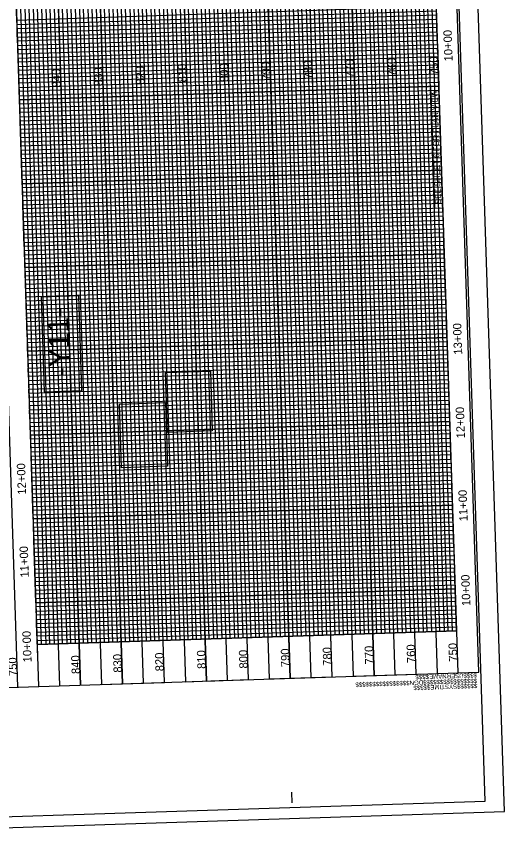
# Model space of a CAD drawing. Extents: x 1627314 to 1628469, y 762309 to 764253.
# Drawn here: x 1627888 to 1628469, y 762309 to 763293 of the extents above; entities that cross this region are included whole.
import ezdxf

# ---------------------------------------------------------------- set-up
doc = ezdxf.new("R2010")
doc.units = 0
for name, color, linetype in [('Exist Vertical Profile Horizontal Axis Label Major', 7, 'Continuous'), ('Exist Vertical Profile Vertical Axis Label', 7, 'Continuous'), ('Prop DSN Text', 7, 'Continuous'), ('Prop Grid Mask', 7, 'Continuous'), ('Sheet Data Field CELL', 7, 'Continuous'), ('Sheet DOT Grid CELL', 7, 'Continuous'), ('Sheet Layout Profile Border Port 2', 7, 'Continuous'), ('Sheet Plot Border Inside CELL', 7, 'Continuous'), ('Sheet Plot Border Outside CELL', 7, 'Continuous'), ('Sheet Profile CELL', 7, 'Continuous'), ('Sheet Profile Grid Major CELL', 7, 'Continuous'), ('Sheet Profile Grid Middle CELL', 7, 'Continuous'), ('Sheet Profile Grid Minor CELL', 7, 'Continuous')]:
    doc.layers.add(name, color=color, linetype=linetype)

msp = doc.modelspace()

# ---------------------------------------------------------------- linework, layer by layer
at = {"layer": 'Prop Grid Mask'}
for points in [[(1627891.16, 763193.83), (1627889.52, 763243.8), (1628389.25, 763260.15), (1628390.89, 763210.18)], [(1628380.89, 763209.85), (1628385.63, 763064.93), (1628395.63, 763065.25), (1628390.89, 763210.18)], [(1627965.43, 762847.15), (1627961.73, 762960.18), (1627917.01, 762958.71), (1627920.71, 762845.69)], [(1628067.5, 762797.23), (1628065.17, 762868.61), (1628118.63, 762870.36), (1628120.96, 762798.98)], [(1628012.62, 762755.07), (1628010.14, 762831.14), (1628065.23, 762832.94), (1628067.71, 762756.87)]]:
    msp.add_lwpolyline(points, close=True, dxfattribs=at)
at = {"layer": 'Sheet DOT Grid CELL'}
for p, q in [((1628163.91, 762502.38), (1628114.87, 764001.46)), ((1628213.88, 762504.01), (1628164.85, 764003.1)), ((1628263.85, 762505.65), (1628214.82, 764004.73)), ((1628313.83, 762507.28), (1628264.79, 764006.37)), ((1628363.8, 762508.92), (1628314.77, 764008)), ((1627914.04, 762494.2), (1627865.01, 763993.29)), ((1627964.01, 762495.84), (1627914.98, 763994.92)), ((1628013.99, 762497.47), (1627964.95, 763996.56)), ((1628063.96, 762499.11), (1628014.93, 763998.19)), ((1628113.93, 762500.74), (1628064.9, 763999.83)), ((1627889.52, 763243.8), (1628389.25, 763260.15)), ((1627891.16, 763193.83), (1628390.89, 763210.18)), ((1627892.79, 763143.86), (1628392.52, 763160.2)), ((1627894.43, 763093.88), (1628394.16, 763110.23)), ((1627896.06, 763043.91), (1628395.79, 763060.26)), ((1627897.69, 762993.94), (1628397.43, 763010.28)), ((1627899.33, 762943.96), (1628399.06, 762960.31)), ((1627900.96, 762893.99), (1628400.7, 762910.34)), ((1627902.6, 762844.02), (1628402.33, 762860.36)), ((1627904.23, 762794.04), (1628403.97, 762810.39)), ((1627905.87, 762744.07), (1628405.6, 762760.42)), ((1627907.5, 762694.1), (1628407.24, 762710.44)), ((1627909.14, 762644.12), (1628408.87, 762660.47)), ((1627910.77, 762594.15), (1628410.5, 762610.5)), ((1627912.41, 762544.18), (1628412.14, 762560.52))]:
    msp.add_line(p, q, dxfattribs=at)
at = {"layer": 'Sheet Layout Profile Border Port 2'}
msp.add_lwpolyline([(1627912.41, 762544.18), (1627866.64, 763943.43), (1628366.37, 763959.78), (1628412.14, 762560.52)], close=True, dxfattribs=at)
at = {"layer": 'Sheet Plot Border Inside CELL'}
msp.add_lwpolyline([(1628446.34, 762357.53), (1628391.86, 764023.14), (1627337.33, 763988.65), (1627391.81, 762323.04)], close=True, dxfattribs=at)
at = {"layer": 'Sheet Plot Border Outside CELL'}
msp.add_lwpolyline([(1628469.21, 762345.27), (1628413.63, 764044.37), (1627314.22, 764008.4), (1627369.79, 762309.31)], close=True, dxfattribs=at)
at = {"layer": 'Sheet Profile CELL'}
for p, q in [((1628364.74, 764009.75), (1628413.77, 762510.55)), ((1628438.76, 762511.37), (1628389.72, 764010.57)), ((1627889.05, 762493.39), (1627840.02, 763992.59)), ((1627914.04, 762494.2), (1627865, 763993.4)), ((1628438.76, 762511.37), (1628438.76, 762511.37)), ((1628438.76, 762511.37), (1628438.76, 762511.37)), ((1628438.76, 762511.37), (1628438.76, 762511.37)), ((1628438.76, 762511.37), (1628438.76, 762511.37)), ((1628438.76, 762511.37), (1628438.76, 762511.37)), ((1628438.76, 762511.37), (1628438.76, 762511.37)), ((1628438.76, 762511.37), (1628438.76, 762511.37)), ((1628216.24, 762355.51), (1628215.83, 762368))]:
    msp.add_line(p, q, dxfattribs=at)
msp.add_lwpolyline([(1627340.28, 763976.24), (1627389.32, 762477.04), (1628438.76, 762511.37), (1628389.72, 764010.57)], close=True, dxfattribs=at)
msp.add_lwpolyline([(1628437.53, 762548.85), (1628437.53, 762548.85)], dxfattribs=at)
at = {"layer": 'Sheet Profile Grid Major CELL'}
for p, q in [((1627891.16, 763193.83), (1627889.52, 763243.8)), ((1627894.43, 763093.88), (1627892.79, 763143.86)), ((1627897.69, 762993.94), (1627896.06, 763043.91)), ((1628413.77, 762510.55), (1628413.77, 762510.55))]:
    msp.add_line(p, q, dxfattribs=at)
for points in [[(1628064.9, 763999.94), (1628113.93, 762500.74), (1628163.91, 762502.38), (1628114.87, 764001.58)], [(1628164.84, 764003.21), (1628213.88, 762504.01), (1628263.85, 762505.65), (1628214.82, 764004.85)], [(1628264.79, 764006.48), (1628313.83, 762507.28), (1628313.83, 762507.28), (1628363.8, 762508.92), (1628314.76, 764008.11)], [(1628364.74, 764009.75), (1628413.77, 762510.55)], [(1627914.98, 763995.04), (1627964.01, 762495.84)], [(1627964.95, 763996.67), (1628013.99, 762497.47), (1628063.96, 762499.11), (1628014.92, 763998.31)], [(1627912.41, 762544.18), (1628412.14, 762560.52), (1628410.5, 762610.5), (1627910.77, 762594.15), (1627909.14, 762644.12), (1628408.87, 762660.47), (1628407.24, 762710.44), (1627907.5, 762694.1), (1627905.87, 762744.07), (1628405.6, 762760.42), (1628403.97, 762810.39), (1627904.23, 762794.04), (1627902.6, 762844.02), (1628402.33, 762860.36), (1628400.7, 762910.34), (1627900.96, 762893.99), (1627899.33, 762943.96), (1628399.06, 762960.31), (1628397.43, 763010.28), (1627897.69, 762993.94), (1627896.06, 763043.91), (1628395.79, 763060.26), (1628394.16, 763110.23), (1627894.43, 763093.88), (1627892.79, 763143.86), (1628392.52, 763160.2), (1628390.89, 763210.18), (1627891.16, 763193.83), (1627889.52, 763243.8), (1628389.25, 763260.15), (1628387.62, 763310.12)]]:
    msp.add_lwpolyline(points, dxfattribs=at)
at = {"layer": 'Sheet Profile Grid Middle CELL'}
for points in [[(1628139.86, 764002.39), (1628188.89, 762503.2), (1628238.87, 762504.83), (1628189.83, 764004.03)], [(1628239.8, 764005.66), (1628288.84, 762506.46), (1628338.81, 762508.1), (1628289.78, 764007.3)], [(1628339.75, 764008.93), (1628388.79, 762509.73)], [(1627939.03, 762495.02), (1627889.99, 763994.22)], [(1627939.96, 763995.85), (1627989, 762496.66), (1628038.97, 762498.29), (1627989.94, 763997.49)], [(1628039.91, 763999.12), (1628088.95, 762499.93), (1628138.92, 762501.56), (1628089.88, 764000.76)], [(1627913.22, 762519.19), (1627911.59, 762569.16), (1628411.32, 762585.51), (1628409.69, 762635.48), (1627909.95, 762619.14), (1627908.32, 762669.11), (1628408.05, 762685.46), (1628406.42, 762735.43), (1627906.69, 762719.08), (1627905.05, 762769.06), (1628404.78, 762785.4), (1628403.15, 762835.38), (1627903.42, 762819.03), (1627901.78, 762869), (1628401.51, 762885.35), (1628399.88, 762935.32), (1627900.15, 762918.98), (1627898.51, 762968.95), (1628398.24, 762985.3), (1628396.61, 763035.27), (1627896.88, 763018.92), (1627895.24, 763068.9), (1628394.98, 763085.24), (1628393.34, 763135.22), (1628393.34, 763135.22), (1627893.61, 763118.87), (1627891.97, 763168.84), (1628391.71, 763185.19), (1628390.07, 763235.16), (1627890.34, 763218.82), (1627888.7, 763268.79), (1628388.44, 763285.14), (1628386.8, 763335.11)]]:
    msp.add_lwpolyline(points, dxfattribs=at)
at = {"layer": 'Sheet Profile Grid Minor CELL'}
for p, q in [((1628167.27, 762552.51), (1628121.5, 763951.77)), ((1628126.5, 763951.93), (1628172.27, 762552.68)), ((1628177.26, 762552.84), (1628131.5, 763952.09)), ((1628136.49, 763952.26), (1628182.26, 762553)), ((1628192.26, 762553.33), (1628146.49, 763952.58)), ((1628151.48, 763952.75), (1628197.25, 762553.5)), ((1628202.25, 762553.66), (1628156.48, 763952.91)), ((1628161.48, 763953.07), (1628207.25, 762553.82)), ((1628217.24, 762554.15), (1628171.47, 763953.4)), ((1628176.47, 763953.56), (1628222.24, 762554.31)), ((1628227.24, 762554.48), (1628181.47, 763953.73)), ((1628186.47, 763953.89), (1628232.24, 762554.64)), ((1628242.23, 762554.97), (1628196.46, 763954.22)), ((1628201.46, 763954.38), (1628247.23, 762555.13)), ((1628252.22, 762555.29), (1628206.46, 763954.55)), ((1628211.45, 763954.71), (1628257.22, 762555.46)), ((1628267.22, 762555.78), (1628221.45, 763955.04)), ((1628226.44, 763955.2), (1628272.21, 762555.95)), ((1628277.21, 762556.11), (1628231.44, 763955.36)), ((1628236.44, 763955.53), (1628282.21, 762556.27)), ((1628292.2, 762556.6), (1628246.43, 763955.85)), ((1628251.43, 763956.02), (1628297.2, 762556.76)), ((1628302.2, 762556.93), (1628256.43, 763956.18)), ((1628261.43, 763956.34), (1628307.2, 762557.09)), ((1628317.19, 762557.42), (1628271.42, 763956.67)), ((1628276.42, 763956.83), (1628322.19, 762557.58)), ((1628327.18, 762557.75), (1628281.42, 763957)), ((1628286.41, 763957.16), (1628332.18, 762557.91)), ((1628342.18, 762558.24), (1628296.41, 763957.49)), ((1628301.4, 763957.65), (1628347.17, 762558.4)), ((1628352.17, 762558.56), (1628306.4, 763957.81)), ((1628311.4, 763957.98), (1628357.17, 762558.73)), ((1628367.16, 762559.05), (1628321.39, 763958.3)), ((1628326.39, 763958.47), (1628372.16, 762559.22)), ((1628377.16, 762559.38), (1628331.39, 763958.63)), ((1628336.39, 763958.8), (1628382.16, 762559.54)), ((1628392.15, 762559.87), (1628346.38, 763959.12)), ((1628351.38, 763959.29), (1628397.15, 762560.03)), ((1628402.14, 762560.2), (1628356.37, 763959.45)), ((1628407.14, 762560.36), (1628361.37, 763959.61)), ((1627917.4, 762544.34), (1627871.63, 763943.59)), ((1627876.63, 763943.76), (1627922.4, 762544.5)), ((1627927.4, 762544.67), (1627881.63, 763943.92)), ((1627886.63, 763944.08), (1627932.4, 762544.83)), ((1627942.39, 762545.16), (1627896.62, 763944.41)), ((1627901.62, 763944.57), (1627947.39, 762545.32)), ((1627952.38, 762545.49), (1627906.62, 763944.74)), ((1627911.61, 763944.9), (1627957.38, 762545.65)), ((1627967.38, 762545.98), (1627921.61, 763945.23)), ((1627926.6, 763945.39), (1627972.37, 762546.14)), ((1627977.37, 762546.3), (1627931.6, 763945.55)), ((1627936.6, 763945.72), (1627982.37, 762546.47)), ((1627992.36, 762546.79), (1627946.59, 763946.05)), ((1627951.59, 763946.21), (1627997.36, 762546.96)), ((1628002.36, 762547.12), (1627956.59, 763946.37)), ((1627961.59, 763946.54), (1628007.36, 762547.28)), ((1628017.35, 762547.61), (1627971.58, 763946.86)), ((1627976.58, 763947.03), (1628022.35, 762547.77)), ((1628027.34, 762547.94), (1627981.58, 763947.19)), ((1627986.57, 763947.35), (1628032.34, 762548.1)), ((1628042.34, 762548.43), (1627996.57, 763947.68)), ((1628001.56, 763947.84), (1628047.33, 762548.59)), ((1628052.33, 762548.75), (1628006.56, 763948.01)), ((1628011.56, 763948.17), (1628057.33, 762548.92)), ((1628067.32, 762549.25), (1628021.55, 763948.5)), ((1628026.55, 763948.66), (1628072.32, 762549.41)), ((1628077.32, 762549.57), (1628031.55, 763948.82)), ((1628036.55, 763948.99), (1628082.32, 762549.74)), ((1628092.31, 762550.06), (1628046.54, 763949.31)), ((1628051.54, 763949.48), (1628097.31, 762550.23)), ((1628102.3, 762550.39), (1628056.54, 763949.64)), ((1628061.53, 763949.8), (1628107.15, 762550.55)), ((1628117.3, 762550.88), (1628071.53, 763950.13)), ((1628076.52, 763950.3), (1628122.29, 762551.04)), ((1628127.29, 762551.21), (1628081.52, 763950.46)), ((1628086.52, 763950.62), (1628132.29, 762551.37)), ((1628142.28, 762551.7), (1628096.51, 763950.95)), ((1628101.51, 763951.11), (1628147.28, 762551.86)), ((1628152.28, 762552.02), (1628106.51, 763951.28)), ((1628111.51, 763951.44), (1628157.28, 762552.19))]:
    msp.add_line(p, q, dxfattribs=at)
for points in [[(1628387.78, 763305.13), (1627888.05, 763288.78), (1627887.72, 763298.77)], [(1627895.08, 763073.89), (1628394.81, 763090.24), (1628394.65, 763095.24), (1627894.92, 763078.89), (1627894.75, 763083.89), (1628394.49, 763100.24), (1628394.32, 763105.23), (1627894.59, 763088.89), (1627894.26, 763098.88), (1628393.99, 763115.23), (1628393.83, 763120.22), (1627894.1, 763103.88), (1627893.94, 763108.88), (1628393.67, 763125.22), (1628393.5, 763130.22), (1627893.77, 763113.87), (1627893.44, 763123.87), (1628393.18, 763140.21), (1628393.01, 763145.21), (1627893.28, 763128.87), (1627893.12, 763133.86), (1628392.85, 763150.21), (1628392.69, 763155.21), (1627892.95, 763138.86), (1627892.63, 763148.85), (1628392.36, 763165.2), (1628392.2, 763170.2), (1627892.46, 763153.85), (1627892.3, 763158.85), (1628392.03, 763175.2), (1628391.87, 763180.19), (1627892.14, 763163.85), (1627891.81, 763173.84), (1628391.54, 763190.19), (1628391.38, 763195.18), (1627891.65, 763178.84), (1627891.48, 763183.84), (1628391.22, 763200.18), (1628391.05, 763205.18), (1627891.32, 763188.83), (1627890.99, 763198.83), (1628390.73, 763215.17), (1628390.73, 763215.17), (1628390.56, 763220.17), (1627890.83, 763203.83), (1627890.67, 763208.82), (1628390.4, 763225.17), (1628390.24, 763230.17), (1627890.5, 763213.82), (1627890.18, 763223.81), (1628389.91, 763240.16), (1628389.74, 763245.16), (1627890.01, 763228.81), (1627889.85, 763233.81), (1628389.58, 763250.16), (1628389.42, 763255.15), (1627889.69, 763238.81), (1627889.36, 763248.8), (1628389.09, 763265.15), (1628388.93, 763270.14), (1627889.19, 763253.8), (1627889.03, 763258.8), (1628388.76, 763275.14), (1628388.6, 763280.14), (1627888.87, 763263.79), (1627888.54, 763273.79), (1628388.27, 763290.13), (1628388.11, 763295.13), (1627888.38, 763278.79), (1627888.21, 763283.78), (1628387.95, 763300.13)], [(1628405.11, 762775.41), (1628404.95, 762780.41), (1627905.21, 762764.06), (1627904.89, 762774.06), (1628404.62, 762790.4), (1628404.46, 762795.4), (1627904.72, 762779.05), (1627904.56, 762784.05), (1628404.29, 762800.4), (1628404.13, 762805.39), (1627904.4, 762789.05), (1627904.07, 762799.04), (1628403.8, 762815.39), (1628403.64, 762820.39), (1627903.91, 762804.04), (1627903.74, 762809.04), (1628403.48, 762825.38), (1628403.31, 762830.38), (1627903.58, 762814.03), (1627903.25, 762824.03), (1628402.99, 762840.37), (1628402.82, 762845.37), (1627903.09, 762829.03), (1627902.93, 762834.02), (1628402.66, 762850.37), (1628402.49, 762855.37), (1627902.76, 762839.02), (1627902.44, 762849.01), (1628402.17, 762865.36), (1628402, 762870.36), (1627902.27, 762854.01), (1627902.11, 762859.01), (1628401.84, 762875.36), (1628401.68, 762880.35), (1627901.94, 762864.01), (1627901.62, 762874), (1628401.35, 762890.35), (1628401.19, 762895.35), (1627901.45, 762879), (1627901.29, 762884), (1628401.02, 762900.34), (1628400.86, 762905.34), (1627901.13, 762888.99), (1627900.8, 762898.99), (1628400.53, 762915.33), (1628400.37, 762920.33), (1627900.64, 762903.99), (1627900.47, 762908.98), (1628400.21, 762925.33), (1628400.04, 762930.33), (1627900.31, 762913.98), (1627899.98, 762923.97), (1628399.72, 762940.32), (1628399.55, 762945.32), (1627899.82, 762928.97), (1627899.66, 762933.97), (1628399.39, 762950.32), (1628399.23, 762955.31), (1627899.49, 762938.97), (1627899.17, 762948.96), (1628398.9, 762965.31), (1628398.74, 762970.31), (1627899, 762953.96), (1627898.84, 762958.96), (1628398.57, 762975.3), (1628398.41, 762980.3), (1627898.68, 762963.95), (1627898.35, 762973.95), (1628398.08, 762990.29), (1628397.92, 762995.29), (1627898.19, 762978.95), (1627898.02, 762983.94), (1628397.75, 763000.29), (1628397.59, 763005.29), (1627897.86, 762988.94), (1627897.53, 762998.93), (1628397.26, 763015.28), (1628397.1, 763020.28), (1627897.37, 763003.93), (1627897.2, 763008.93), (1628396.94, 763025.28), (1628396.77, 763030.27), (1627897.04, 763013.93), (1627896.71, 763023.92), (1628396.45, 763040.27), (1628396.28, 763045.26), (1627896.55, 763028.92), (1627896.39, 763033.92), (1628396.12, 763050.26), (1628395.96, 763055.26), (1627896.22, 763038.91), (1627895.9, 763048.91), (1628395.63, 763065.25), (1628395.47, 763070.25), (1627895.73, 763053.91), (1627895.57, 763058.9), (1628395.3, 763075.25), (1628395.14, 763080.25), (1627895.41, 763063.9), (1627895.08, 763073.89)], [(1627912.41, 762544.18), (1627912.24, 762549.18), (1628411.98, 762565.52), (1628411.81, 762570.52), (1627912.08, 762554.17), (1627911.92, 762559.17), (1628411.65, 762575.52), (1628411.49, 762580.51), (1627911.75, 762564.17), (1627911.43, 762574.16), (1628411.16, 762590.51), (1628410.99, 762595.51), (1627911.26, 762579.16), (1627911.1, 762584.16), (1628410.83, 762600.5), (1628410.67, 762605.5), (1628410.34, 762615.49), (1628410.18, 762620.49), (1627910.44, 762604.15), (1627910.28, 762609.14), (1628410.01, 762625.49), (1628409.85, 762630.49), (1627910.12, 762614.14), (1627909.79, 762624.14), (1628409.52, 762640.48), (1628409.36, 762645.48), (1627909.63, 762629.13), (1627909.46, 762634.13), (1628409.2, 762650.48), (1628409.03, 762655.47), (1627909.3, 762639.13), (1627908.97, 762649.12), (1628408.71, 762665.47), (1628408.54, 762670.47), (1627908.81, 762654.12), (1627908.65, 762659.12), (1628408.38, 762675.46), (1628408.22, 762680.46), (1627908.48, 762664.11), (1627908.16, 762674.11), (1628407.89, 762690.45), (1628407.73, 762695.45), (1627907.99, 762679.11), (1627907.83, 762684.1), (1628407.56, 762700.45), (1628407.4, 762705.45), (1627907.67, 762689.1), (1627907.34, 762699.1), (1628407.07, 762715.44), (1628406.91, 762720.44), (1627907.18, 762704.09), (1627907.01, 762709.09), (1628406.74, 762725.44), (1628406.58, 762730.43), (1627906.85, 762714.09), (1627906.52, 762724.08), (1628406.25, 762740.43), (1628406.09, 762745.43), (1627906.36, 762729.08), (1627906.19, 762734.08), (1628405.93, 762750.42), (1628405.76, 762755.42), (1627906.03, 762739.07), (1627905.7, 762749.07), (1628405.44, 762765.41), (1628405.27, 762770.41), (1627905.54, 762754.07), (1627905.38, 762759.06), (1628405.11, 762775.41)], [(1628410.67, 762605.5), (1627910.94, 762589.15), (1627910.61, 762599.15), (1628410.34, 762615.49)]]:
    msp.add_lwpolyline(points, dxfattribs=at)

# ---------------------------------------------------------------- texts
at = {"layer": 'Exist Vertical Profile Horizontal Axis Label Major'}
for s, p in [('10+00', (1628407.43, 763239.93)), ('13+00', (1628418.86, 762890.23)), ('12+00', (1628422.13, 762790.29)), ('12+00', (1627899.05, 762723.15)), ('11+00', (1628425.37, 762691.42)), ('11+00', (1627902.28, 762624.28)), ('10+00', (1628428.68, 762590.28)), ('10+00', (1627905.59, 762523.14))]:
    msp.add_text(s, height=10, rotation=91.87347, dxfattribs=at).set_placement(p)
at = {"layer": 'Exist Vertical Profile Vertical Axis Label'}
for s, p in [('760', (1628340.23, 763221.96)), ('750', (1628390.2, 763223.59)), ('820', (1628040.39, 763212.15)), ('810', (1628090.32, 763214.98)), ('800', (1628140.33, 763215.42)), ('790', (1628190.31, 763217.05)), ('780', (1628240.28, 763218.69)), ('770', (1628290.25, 763220.32)), ('840', (1627940.44, 763208.88)), ('830', (1627990.41, 763210.52)), ('750', (1628413.08, 762523.97)), ('810', (1628113.21, 762515.36)), ('800', (1628163.22, 762515.79)), ('790', (1628213.19, 762517.43)), ('780', (1628263.16, 762519.06)), ('770', (1628313.14, 762520.7)), ('760', (1628363.11, 762522.33)), ('750', (1627888.37, 762506.8)), ('840', (1627963.33, 762509.26)), ('830', (1628013.3, 762510.89)), ('820', (1628063.27, 762512.53))]:
    msp.add_text(s, height=10, rotation=91.87347, dxfattribs=at).set_placement(p)
at = {"layer": 'Prop DSN Text'}
msp.add_text('SEE SHEET 6 FOR PLAN VIEW', height=7, rotation=91.87347, dxfattribs=at).set_placement((1628393.53, 763069.77))
at = {"layer": 'Sheet Data Field CELL'}
msp.add_text('-Y11-', height=25, rotation=91.87347, dxfattribs=at).set_placement((1627951.8, 762864.54))
at = {"layer": 'Sheet Profile CELL'}
for s, p in [('$$$$USERNAME$$$$', (1628436.41, 762510.23)), ('$$$$$$$$$$$$$$$$DGN$$$$$$$$$$$$$$$$', (1628436.64, 762503.66)), ('$$$$$$SYSTIME$$$$$', (1628436.83, 762497.61))]:
    msp.add_text(s, height=5.25, rotation=181.87347, dxfattribs=at).set_placement(p)

doc.saveas('drawing.dxf')
